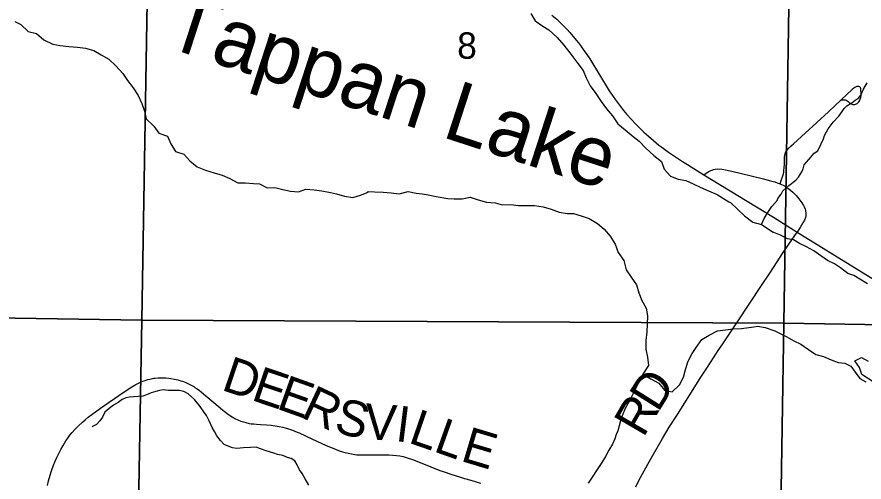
# Model space of a CAD drawing. Extents: x 0 to 34, y 0 to 22.
# Drawn here: x 22.024 to 23.369, y 15.371 to 16.109 of the extents above; entities that cross this region are included whole.
import ezdxf

# ---------------------------------------------------------------- set-up
doc = ezdxf.new("R2010")
doc.units = 0
for name, color, linetype in [('GM_X_Corporation', 7, 'Continuous'), ('GM_X_County_Road', 7, 'Continuous'), ('GM_X_County_Road_Text', 7, 'Continuous'), ('GM_X_Major_Lake', 7, 'Continuous'), ('GM_X_Major_Lake_Text', 7, 'Continuous'), ('GM_X_Minor_River', 7, 'Continuous'), ('GM_X_Section_Text', 7, 'Continuous'), ('GM_X_Township_Road', 7, 'Continuous'), ('GM_X_US_Route', 7, 'Continuous')]:
    doc.layers.add(name, color=color, linetype=linetype)

msp = doc.modelspace()

# ---------------------------------------------------------------- linework, layer by layer
at = {"layer": 'GM_X_Corporation'}
for points in [[(21.2309, 16.6512), (22.2392, 16.6385), (22.2224, 15.6282), (21.2159, 15.6439)], [(23.2579, 16.628), (23.7676, 16.6453), (24.2698, 16.6327), (24.2658, 16.4792), (24.2407, 15.6067), (23.2418, 15.623)], [(22.2392, 16.6385), (23.2579, 16.628), (23.2418, 15.623), (22.2224, 15.6282)], [(22.2224, 15.6282), (22.2045, 14.6168), (21.1958, 14.6279), (21.2159, 15.6439)], [(22.2224, 15.6282), (23.2418, 15.623), (23.2254, 14.5998), (22.2045, 14.6168)], [(23.2418, 15.623), (24.2407, 15.6067), (24.2392, 15.4615), (24.2269, 14.5903), (23.2254, 14.5998)]]:
    msp.add_lwpolyline(points, close=True, dxfattribs=at)
at = {"layer": 'GM_X_County_Road'}
for points in [[(23.1352, 15.5758), (23.1379, 15.5799), (23.1441, 15.589), (23.1673, 15.6235), (23.2077, 15.6846), (23.2176, 15.6992), (23.2268, 15.713), (23.2401, 15.7336), (23.2502, 15.7488), (23.2631, 15.7678)], [(23.0068, 15.3636), (23.012, 15.3735), (23.0288, 15.4043), (23.0327, 15.4117), (23.0492, 15.44), (23.0601, 15.4579), (23.0733, 15.4785), (23.1115, 15.5389), (23.1206, 15.5533), (23.1352, 15.5758)], [(22.0729, 15.3656), (22.0744, 15.3729), (22.0767, 15.3817), (22.079, 15.3886), (22.0824, 15.3977), (22.0851, 15.4042), (22.0875, 15.41), (22.0907, 15.4162), (22.0941, 15.4229), (22.0974, 15.4291), (22.1019, 15.4363), (22.105, 15.4407), (22.1083, 15.4452), (22.1118, 15.4496), (22.1162, 15.4544), (22.122, 15.4604), (22.128, 15.4659), (22.1327, 15.47), (22.1374, 15.4738), (22.1566, 15.4881), (22.1636, 15.4929), (22.1707, 15.4977), (22.1946, 15.5142), (22.2068, 15.522), (22.2131, 15.5259), (22.2182, 15.5287), (22.2222, 15.5304), (22.2261, 15.5319), (22.2319, 15.5337), (22.235, 15.5345), (22.2414, 15.5357), (22.2439, 15.5361), (22.2482, 15.5365), (22.2532, 15.5366), (22.2588, 15.5365), (22.2606, 15.5364), (22.2651, 15.5359), (22.2683, 15.5355), (22.2744, 15.5343), (22.2799, 15.5331), (22.2842, 15.5319), (22.2873, 15.5309), (22.2925, 15.5289), (22.2956, 15.5276), (22.2985, 15.5261), (22.3048, 15.5227), (22.3067, 15.5213), (22.3102, 15.5189), (22.3141, 15.5162), (22.3166, 15.5142), (22.3243, 15.5078), (22.3369, 15.4973), (22.3507, 15.4854), (22.3532, 15.4834), (22.36, 15.4784), (22.3631, 15.4762), (22.3684, 15.4731), (22.3704, 15.4718), (22.375, 15.4697), (22.3797, 15.4678), (22.3838, 15.4664), (22.3879, 15.4653), (22.3929, 15.4642), (22.3961, 15.4636), (22.4002, 15.4632), (22.4047, 15.4629), (22.4108, 15.4625), (22.4207, 15.4618), (22.428, 15.4611), (22.4341, 15.4604), (22.4405, 15.4594), (22.4466, 15.4579), (22.4536, 15.456), (22.4617, 15.4533), (22.4694, 15.4503), (22.4725, 15.449), (22.4937, 15.4393), (22.4992, 15.4366), (22.5096, 15.4318), (22.518, 15.4279), (22.5219, 15.4262), (22.5309, 15.4225), (22.5374, 15.4202), (22.5414, 15.419), (22.5446, 15.4181), (22.5501, 15.4168), (22.5557, 15.4157), (22.5606, 15.4148), (22.5639, 15.4144), (22.5667, 15.4142), (22.5689, 15.4142), (22.5854, 15.414), (22.6121, 15.4142), (22.6148, 15.414), (22.6209, 15.4138), (22.627, 15.4132), (22.632, 15.4125), (22.6376, 15.4114), (22.6441, 15.4096), (22.6524, 15.4066), (22.6594, 15.404), (22.6812, 15.3951), (22.6958, 15.3895), (22.7008, 15.3878), (22.7149, 15.3832), (22.727, 15.3794), (22.7351, 15.3768), (22.7449, 15.3738), (22.7602, 15.3692)]]:
    msp.add_lwpolyline(points, dxfattribs=at)
at = {"layer": 'GM_X_Major_Lake'}
for points in [[(22.8401, 16.1145), (22.847, 16.1028), (22.8592, 16.0946), (22.8691, 16.089), (22.8821, 16.0766), (22.8928, 16.0646), (22.902, 16.0521), (22.9135, 16.0375), (22.9231, 16.0243), (22.9282, 16.0126), (22.9344, 16.0001), (22.9436, 15.9877), (22.952, 15.9752), (22.9604, 15.9632), (22.97, 15.9523), (22.9785, 15.9394), (22.9899, 15.9301), (23.0029, 15.9196), (23.0124, 15.9121), (23.0231, 15.9008), (23.0358, 15.8892), (23.0476, 15.8798), (23.0519, 15.8677), (23.0618, 15.8564), (23.0744, 15.8516), (23.0865, 15.8494), (23.0979, 15.8446), (23.1093, 15.839), (23.1226, 15.8335), (23.136, 15.8272), (23.1547, 15.816)], [(22.0207, 16.102), (22.0302, 16.0972), (22.0421, 16.0863), (22.055, 16.083)], [(22.055, 16.083), (22.0668, 16.0729), (22.0809, 16.0662), (22.093, 16.0641), (22.1067, 16.0623), (22.1204, 16.0613), (22.1332, 16.0599), (22.1462, 16.0559), (22.158, 16.0492), (22.1702, 16.0421), (22.1812, 16.0316), (22.1923, 16.0192), (22.1996, 16.0086), (22.2088, 15.9966), (22.2169, 15.9845), (22.2223, 15.9717), (22.2266, 15.9595), (22.2294, 15.9474), (22.2416, 15.9358), (22.2497, 15.9245), (22.2633, 15.9201), (22.2684, 15.9076), (22.2761, 15.8959), (22.2894, 15.8915), (22.2986, 15.881), (22.3104, 15.8712), (22.3237, 15.866), (22.3374, 15.8616), (22.3503, 15.8579), (22.3621, 15.8528), (22.3747, 15.846), (22.3868, 15.8458), (22.3997, 15.8448), (22.4091, 15.8441), (22.4217, 15.8378), (22.4338, 15.8383), (22.4464, 15.8354), (22.4585, 15.8328), (22.4714, 15.8315), (22.4831, 15.8361), (22.4964, 15.8347), (22.5085, 15.8334), (22.5222, 15.8308), (22.5317, 15.8283), (22.5442, 15.825), (22.5575, 15.8225), (22.5699, 15.8264), (22.582, 15.8311)], [(22.582, 15.8311), (22.5816, 15.8322), (22.5919, 15.8319), (22.6055, 15.8313), (22.6184, 15.8303), (22.6309, 15.8285), (22.6453, 15.8321), (22.6582, 15.8295), (22.6677, 15.8285), (22.6772, 15.8267), (22.6897, 15.8242), (22.7087, 15.8213), (22.7185, 15.8207), (22.7314, 15.8204), (22.7439, 15.8232), (22.7568, 15.8188), (22.7697, 15.8155), (22.7834, 15.8141), (22.7947, 15.8112), (22.8084, 15.8117), (22.8209, 15.8099), (22.8459, 15.8102), (22.8599, 15.8077), (22.8725, 15.804), (22.885, 15.7996), (22.8983, 15.797), (22.9078, 15.7971), (22.9203, 15.7935), (22.9329, 15.7894), (22.9462, 15.7816), (22.9569, 15.7726), (22.9661, 15.7613), (22.9741, 15.7485), (22.9788, 15.7352), (22.988, 15.7224), (22.9915, 15.7076), (22.9996, 15.696), (23.0081, 15.6839), (23.012, 15.6714), (23.0166, 15.6593), (23.0232, 15.6468), (23.0255, 15.6347), (23.0249, 15.6218), (23.0246, 15.6093), (23.0229, 15.5956), (23.023, 15.5819), (23.0257, 15.569), (23.027, 15.5558), (23.018, 15.5424), (23.0306, 15.5349), (23.0435, 15.5278), (23.0523, 15.5169), (23.0649, 15.514), (23.0761, 15.5255), (23.0825, 15.5377), (23.0854, 15.5476), (23.0895, 15.5617), (23.0965, 15.5751), (23.1029, 15.5846), (23.1119, 15.5972), (23.1236, 15.6042), (23.1368, 15.6108), (23.1492, 15.6128), (23.1617, 15.6144), (23.1746, 15.6146), (23.1943, 15.6176)], [(23.1547, 15.816), (23.1573, 15.8145), (23.1684, 15.8043), (23.1798, 15.7934)], [(23.1798, 15.7934), (23.1928, 15.7837), (23.2065, 15.7797), (23.2249, 15.7676)], [(23.3749, 15.6857), (23.3627, 15.6932), (23.3532, 15.6988), (23.3437, 15.7022), (23.3322, 15.7108), (23.3227, 15.7172), (23.3113, 15.7224), (23.3006, 15.7299), (23.2899, 15.7382), (23.2778, 15.7445), (23.2671, 15.7494), (23.2572, 15.7554), (23.2477, 15.7568), (23.2367, 15.7628), (23.2264, 15.7669), (23.2249, 15.7676)], [(23.1943, 15.6176), (23.2003, 15.6186), (23.2125, 15.6165), (23.2277, 15.6112)], [(23.2277, 15.6112), (23.2467, 15.6015), (23.2578, 15.5951), (23.2688, 15.5899), (23.281, 15.5816), (23.2928, 15.5734), (23.305, 15.5701), (23.3171, 15.5652), (23.3285, 15.5608), (23.3388, 15.5597), (23.3483, 15.5552), (23.3552, 15.5454), (23.3629, 15.5352), (23.3724, 15.53)], [(23.3856, 15.529), (23.3658, 15.5417), (23.3623, 15.5531), (23.355, 15.5633), (23.3656, 15.5687), (23.3759, 15.5631)]]:
    msp.add_lwpolyline(points, dxfattribs=at)
at = {"layer": 'GM_X_Minor_River'}
for points in [[(23.2324, 15.8212), (23.2377, 15.828), (23.2404, 15.833), (23.2499, 15.8417), (23.2612, 15.8501), (23.2654, 15.8551), (23.2707, 15.8634), (23.2726, 15.8684), (23.2744, 15.8745), (23.282, 15.8829), (23.29, 15.8928), (23.296, 15.8966), (23.3013, 15.9076), (23.3051, 15.9156), (23.3066, 15.9209), (23.31, 15.927), (23.3126, 15.9316), (23.3206, 15.9422), (23.3293, 15.9517), (23.3346, 15.959), (23.3376, 15.9639), (23.3421, 15.9681), (23.3501, 15.9727), (23.3554, 15.9769), (23.3603, 15.9796), (23.3645, 15.9849), (23.3686, 15.9948), (23.3743, 16.0047)], [(23.2065, 15.7797), (23.211, 15.7892), (23.2166, 15.799), (23.2229, 15.8085), (23.2316, 15.818), (23.2324, 15.8212)], [(23.018, 15.5424), (22.9975, 15.5008), (22.9946, 15.4962), (22.9901, 15.4877), (22.9854, 15.4762), (22.9824, 15.4682), (22.9803, 15.4601), (22.9785, 15.4521), (22.9759, 15.4463), (22.9737, 15.4398), (22.9701, 15.431), (22.9642, 15.4214), (22.959, 15.4114), (22.9531, 15.4018), (22.9456, 15.391), (22.9379, 15.3787), (22.9315, 15.3694)], [(22.4875, 15.3661), (22.4821, 15.3763), (22.477, 15.3846), (22.4728, 15.3906), (22.4689, 15.3986), (22.4654, 15.4046), (22.4597, 15.4083), (22.4536, 15.4098), (22.4463, 15.4131), (22.438, 15.4145), (22.4319, 15.4167), (22.4201, 15.4207), (22.411, 15.424), (22.4038, 15.4262), (22.3951, 15.426), (22.3837, 15.4251), (22.3735, 15.4245), (22.3667, 15.4252), (22.3594, 15.4278), (22.3533, 15.4307), (22.3476, 15.4371), (22.3414, 15.4443), (22.3379, 15.4511), (22.3344, 15.4575), (22.3294, 15.4681), (22.3251, 15.4768), (22.3212, 15.4824), (22.315, 15.4911), (22.3062, 15.502), (22.2958, 15.511), (22.289, 15.5147), (22.2817, 15.5165), (22.2647, 15.5162), (22.2564, 15.5173), (22.2507, 15.5164), (22.2447, 15.5148), (22.2375, 15.5128), (22.23, 15.5092), (22.2239, 15.5072), (22.2168, 15.5068), (22.2031, 15.5058), (22.1971, 15.5045), (22.1915, 15.5018), (22.1847, 15.4975), (22.1776, 15.4932), (22.1704, 15.4878), (22.1637, 15.4819), (22.16, 15.4739), (22.156, 15.4681), (22.1507, 15.4623), (22.1432, 15.4584)]]:
    msp.add_lwpolyline(points, dxfattribs=at)
at = {"layer": 'GM_X_Township_Road'}
for points in [[(23.236, 15.8442), (23.2379, 15.8494), (23.2406, 15.8573), (23.2413, 15.86), (23.2418, 15.863), (23.2423, 15.8659), (23.2426, 15.8694), (23.2429, 15.8766), (23.2432, 15.8867), (23.2441, 15.8921), (23.2443, 15.8928), (23.2452, 15.8949), (23.2459, 15.8961), (23.2492, 15.9004), (23.25, 15.9013), (23.2572, 15.908), (23.3129, 15.9586), (23.3242, 15.9692), (23.3315, 15.976), (23.3325, 15.9769), (23.3333, 15.9777), (23.3371, 15.9778), (23.3398, 15.9775), (23.3408, 15.9772), (23.3417, 15.9768), (23.3427, 15.9761), (23.344, 15.975), (23.3465, 15.9728), (23.3481, 15.9717), (23.3498, 15.9709), (23.3512, 15.9705), (23.3528, 15.9703), (23.3545, 15.9704), (23.3559, 15.9707), (23.3576, 15.9714), (23.3586, 15.9721), (23.3597, 15.973), (23.361, 15.9744), (23.3621, 15.9759), (23.3629, 15.9772), (23.3635, 15.9788), (23.3642, 15.9814), (23.3646, 15.9843), (23.3647, 15.9869), (23.3644, 15.9941), (23.3641, 15.9955), (23.3639, 15.9963), (23.3636, 15.997), (23.3632, 15.9976), (23.3626, 15.9981), (23.362, 15.9984), (23.3611, 15.9987), (23.3603, 15.9989), (23.3578, 15.9987), (23.3568, 15.9983), (23.3548, 15.9972), (23.3532, 15.996), (23.3507, 15.9939), (23.3338, 15.9782), (23.3333, 15.9777)], [(23.1149, 15.8587), (23.1203, 15.8625), (23.1228, 15.864), (23.126, 15.8655), (23.1282, 15.8663), (23.1301, 15.8669), (23.1328, 15.8674), (23.1373, 15.8679), (23.1434, 15.8676), (23.1465, 15.8671), (23.1595, 15.8642), (23.1903, 15.857), (23.2097, 15.8523), (23.2188, 15.8499), (23.2252, 15.8481), (23.2276, 15.8474), (23.2315, 15.8459), (23.236, 15.8442), (23.2381, 15.8433), (23.2408, 15.842), (23.2439, 15.8404), (23.2473, 15.8382), (23.2498, 15.8363), (23.2562, 15.8309), (23.2596, 15.8277), (23.2614, 15.8259), (23.2658, 15.8205), (23.2705, 15.8143), (23.2733, 15.8102), (23.2745, 15.808), (23.276, 15.8043), (23.2766, 15.8021), (23.2771, 15.7979), (23.2771, 15.7934), (23.2763, 15.7907), (23.2746, 15.7867), (23.2723, 15.7824), (23.2678, 15.7752), (23.2631, 15.7678)]]:
    msp.add_lwpolyline(points, dxfattribs=at)
at = {"layer": 'GM_X_US_Route'}
msp.add_lwpolyline([(22.8735, 16.1123), (22.8814, 16.1055), (22.8885, 16.0987), (22.8936, 16.0937), (22.8977, 16.0895), (22.9023, 16.0844), (22.9076, 16.0782), (22.9125, 16.0722), (22.9158, 16.0682), (22.9191, 16.064), (22.9236, 16.0575), (22.9293, 16.0495), (22.9338, 16.0425), (22.9649, 15.9918), (22.9674, 15.988), (22.9747, 15.9778), (22.9796, 15.9713), (22.9876, 15.9607), (22.9927, 15.9546), (22.9997, 15.9468), (23.0069, 15.9391), (23.0128, 15.9331), (23.0197, 15.9266), (23.0272, 15.9198), (23.0349, 15.9129), (23.0437, 15.9058), (23.0481, 15.9024), (23.0591, 15.8945), (23.0699, 15.887), (23.081, 15.8799), (23.0888, 15.8751), (23.1149, 15.8587), (23.2257, 15.7912), (23.2631, 15.7678), (23.4591, 15.6472)], dxfattribs=at)

# ---------------------------------------------------------------- texts
at = {"layer": 'GM_X_County_Road_Text'}
for s, rotation, p in [('D', 341.3185, (22.3471, 15.5178)), ('E', 341.2791, (22.3945, 15.5018)), ('E', 340.4035, (22.4345, 15.4882)), ('D', 57.8529, (23.0421, 15.4802)), ('R', 335.0602, (22.4733, 15.4745)), ('S', 345.1522, (22.5258, 15.4511)), ('R', 59.879, (23.0189, 15.4403)), ('V', 356.4007, (22.5749, 15.4393)), ('I', 352.8547, (22.6239, 15.4363)), ('L', 340.9525, (22.644, 15.4341)), ('L', 340.4577, (22.684, 15.4203)), ('E', 343.2425, (22.727, 15.4051))]:
    msp.add_text(s, height=0.0568, rotation=rotation, dxfattribs=at).set_placement(p)
at = {"layer": 'GM_X_Major_Lake_Text'}
msp.add_text('Tappan Lake', height=0.09469, rotation=341.9624, dxfattribs=at).set_placement((22.2549, 16.0633))
at = {"layer": 'GM_X_Section_Text'}
msp.add_text('8', height=0.0419, rotation=0, dxfattribs=at).set_placement((22.7233, 16.0429))

doc.saveas('drawing.dxf')
